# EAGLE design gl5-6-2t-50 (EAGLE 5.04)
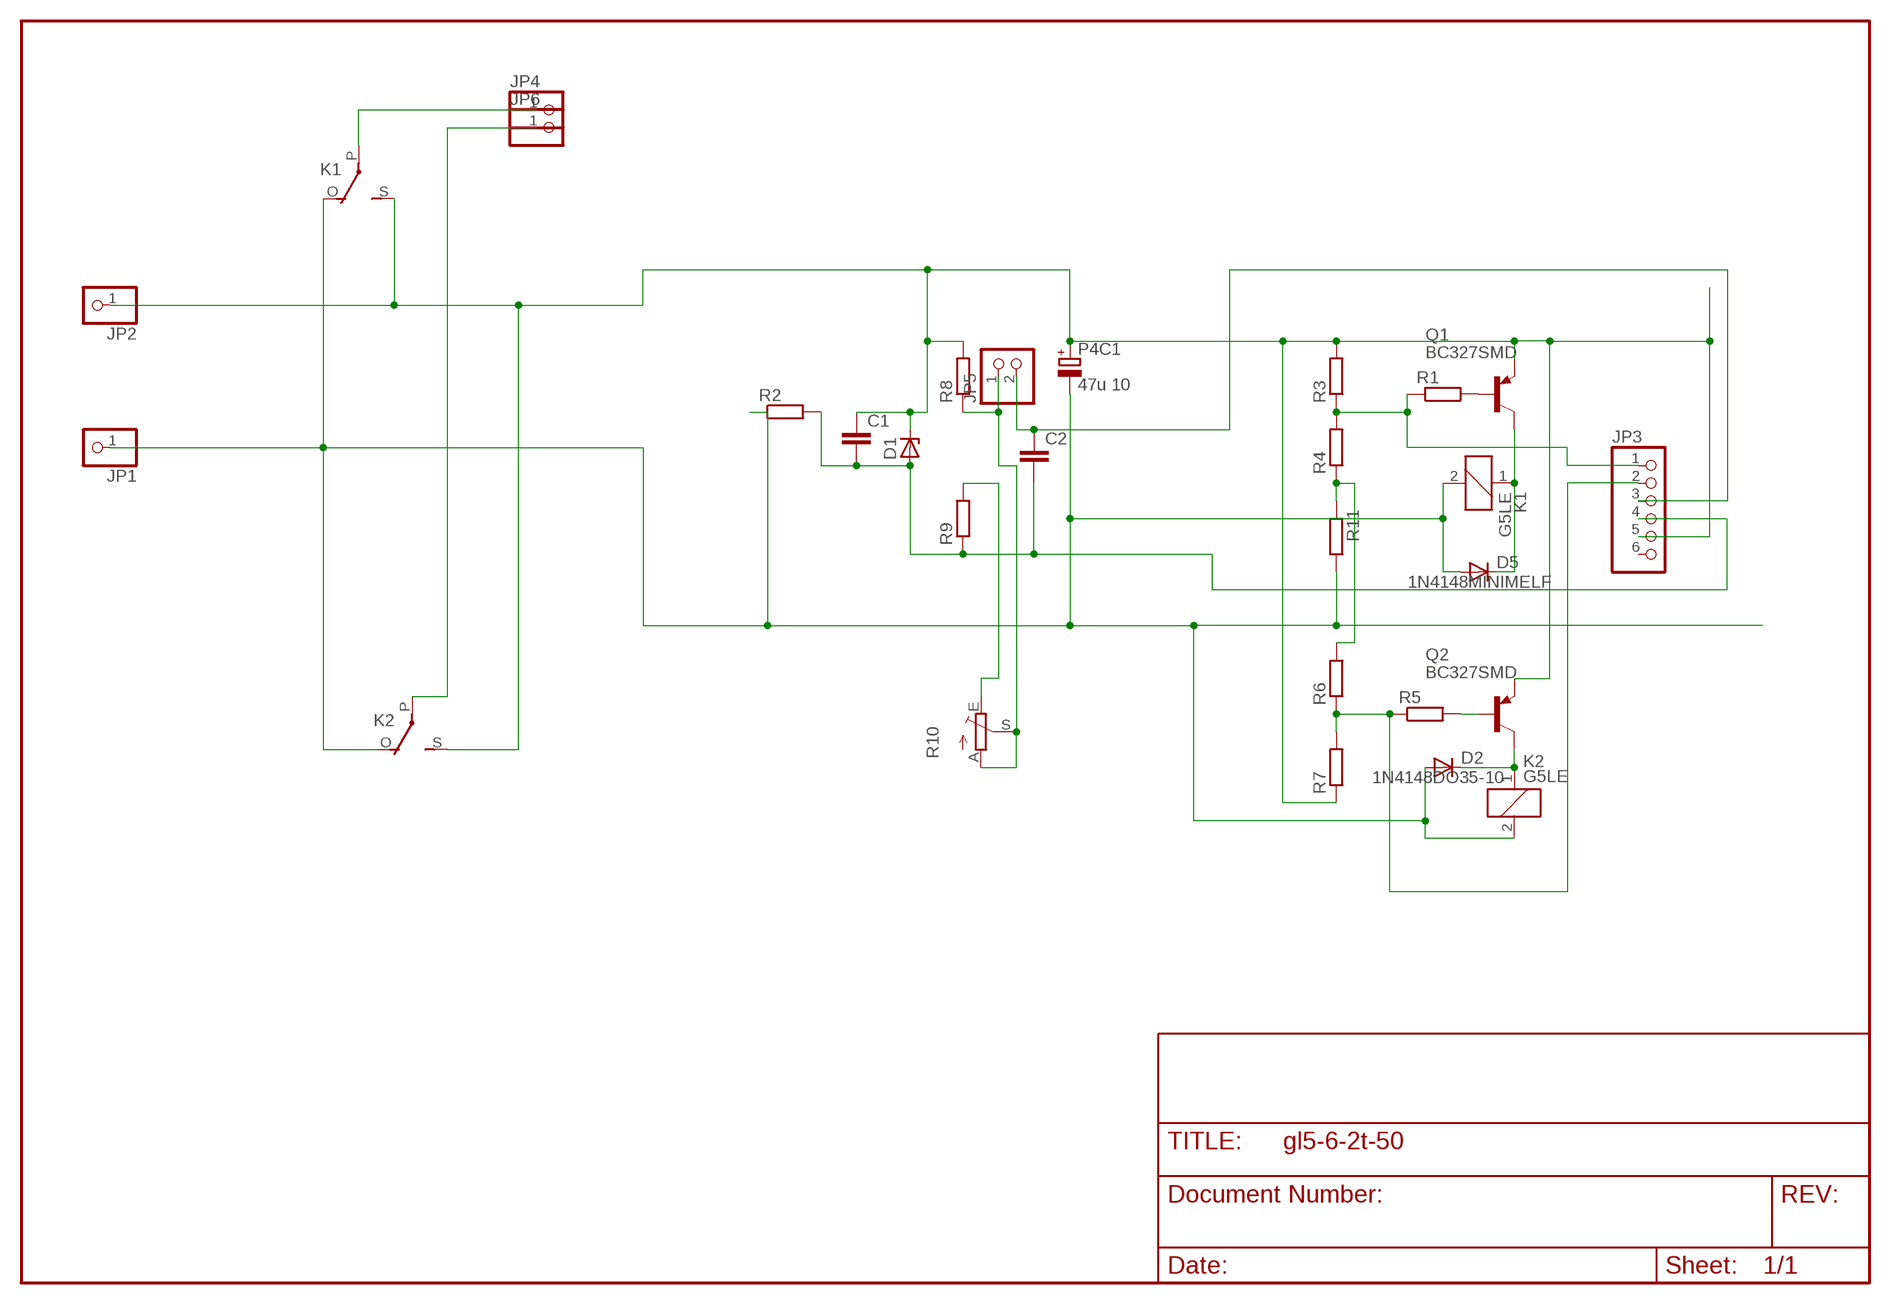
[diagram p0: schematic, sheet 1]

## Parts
C1  C-EUC1206  [C1206]
C2  C-EUC1206  [C1206]
D1  ZENER-DIODESOT23  [SOT23]
D2  1N4148DO35-10  [DO35-10]
D5  1N4148MINIMELF  [MINIMELF]
JP1  PINHD-1X1  [1X01]
JP2  PINHD-1X1  [1X01]
JP3  PINHD-1X6  [1X06]
JP4  PINHD-1X1  [1X01]
JP5  PINHD-1X2  [1X02]
JP6  PINHD-1X1  [1X01]
K1  G5LE  [G5LE]
K2  G5LE  [G5LE]
P4C1  47u 10  CPOL-EUE5-8.5  [E5-8,5]
Q1  BC327SMD  [SOT23-BEC]
Q2  BC327SMD  [SOT23-BEC]
R1  R-EU_R0805  [R0805]
R2  R-EU_M1206  [M1206]
R3  R-EU_R0805  [R0805]
R4  R-EU_R2010  [R2010]
R5  R-EU_R0805  [R0805]
R6  R-EU_R2010  [R2010]
R7  R-EU_R0805  [R0805]
R8  R-EU_R0805  [R0805]
R9  R-EU_R0805  [R0805]
R10  TRIM_EU-CA6V  [CA6V]
R11  R-EU_R0805  [R0805]

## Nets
N$1: R9.2 R10.E
N$2: JP4.1 K1.P(2:P)
N$3: JP5.1 R8.1 R10.A R10.S
N$4: JP6.1 K2.P(2:P)
N$5: C1.2 C2.2 D1.1(A) JP3.4 R2.2 R9.1
N$6: R4.1 R6.2 R11.1
N$7: C2.1 JP3.3 JP5.2
N$8: Q1.B R1.2
N$10: JP3.1 R1.1 R3.1 R4.2
N$11: D5.C K1.1 Q1.C
N$12: D2.C K2.1 Q2.C
N$13: JP3.2 R5.1 R6.1 R7.2
N$15: Q2.B R5.2
V+: C1.1 D1.3(C) JP2.1 JP3.5 K1.S(2:S) K2.S(2:S) P4C1.+ Q1.E Q2.E R3.2 R7.1 R8.2
V-: D2.A D5.A JP1.1 K1.2 K1.O(2:O) K2.2 K2.O(2:O) P4C1.- R2.1 R11.2
Unconnected: JP3.6

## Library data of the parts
C1 C2 = rcl-2:C-EU: CAPACITOR, European symbol
D1 = diode-1:ZENER-DIODE: Z-Diode
D2 D5 = diode-1:1N4148: DIODE
JP1 JP2 JP4 JP6 = pinhead(2):PINHD-1X1: PIN HEADER
JP3 = pinhead:PINHD-1X6: PIN HEADER
JP5 = pinhead:PINHD-1X2: PIN HEADER
K1 K2 = relay:G5LE: RELAY 1 x switch, 10 A/120 V AC, 8 A/30 V DC, Omron
P4C1 = rcl:CPOL-EU: POLARIZED CAPACITOR, European symbol
Q1 Q2 = transistor-pnp:BC327*: PNP Transistror
R1-R9 R11 = rcl-2:R-EU_: RESISTOR, European symbol
R10 = pot:TRIM_EU-: POTENTIOMETER

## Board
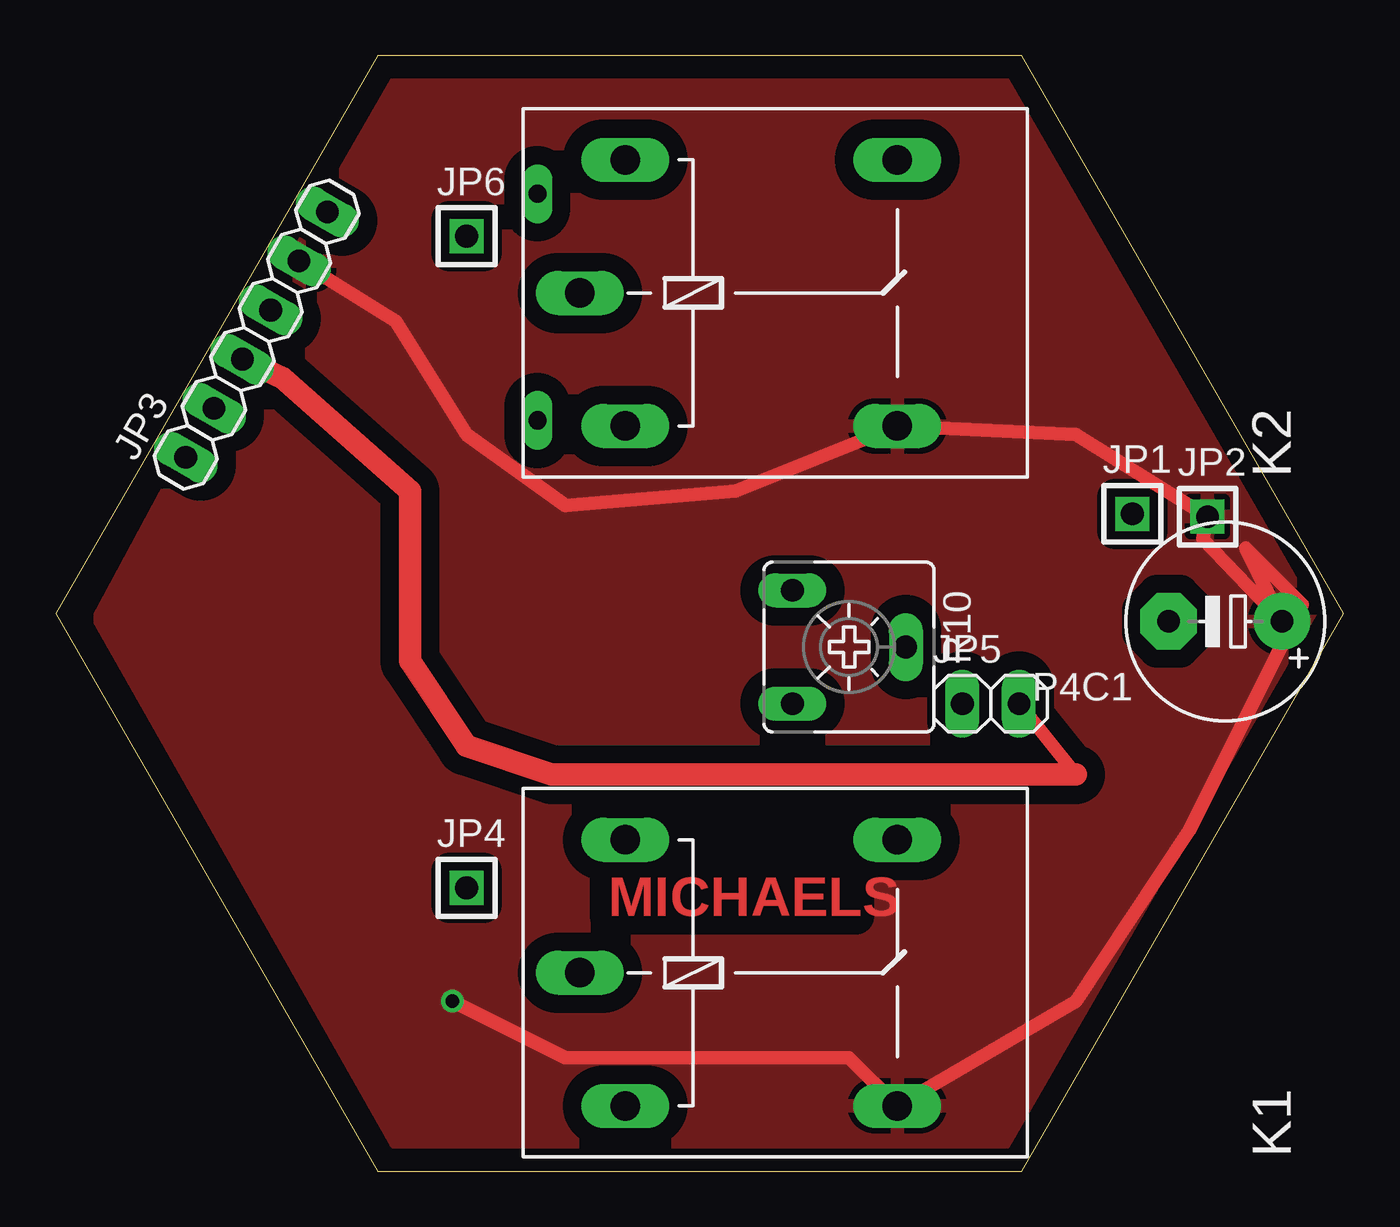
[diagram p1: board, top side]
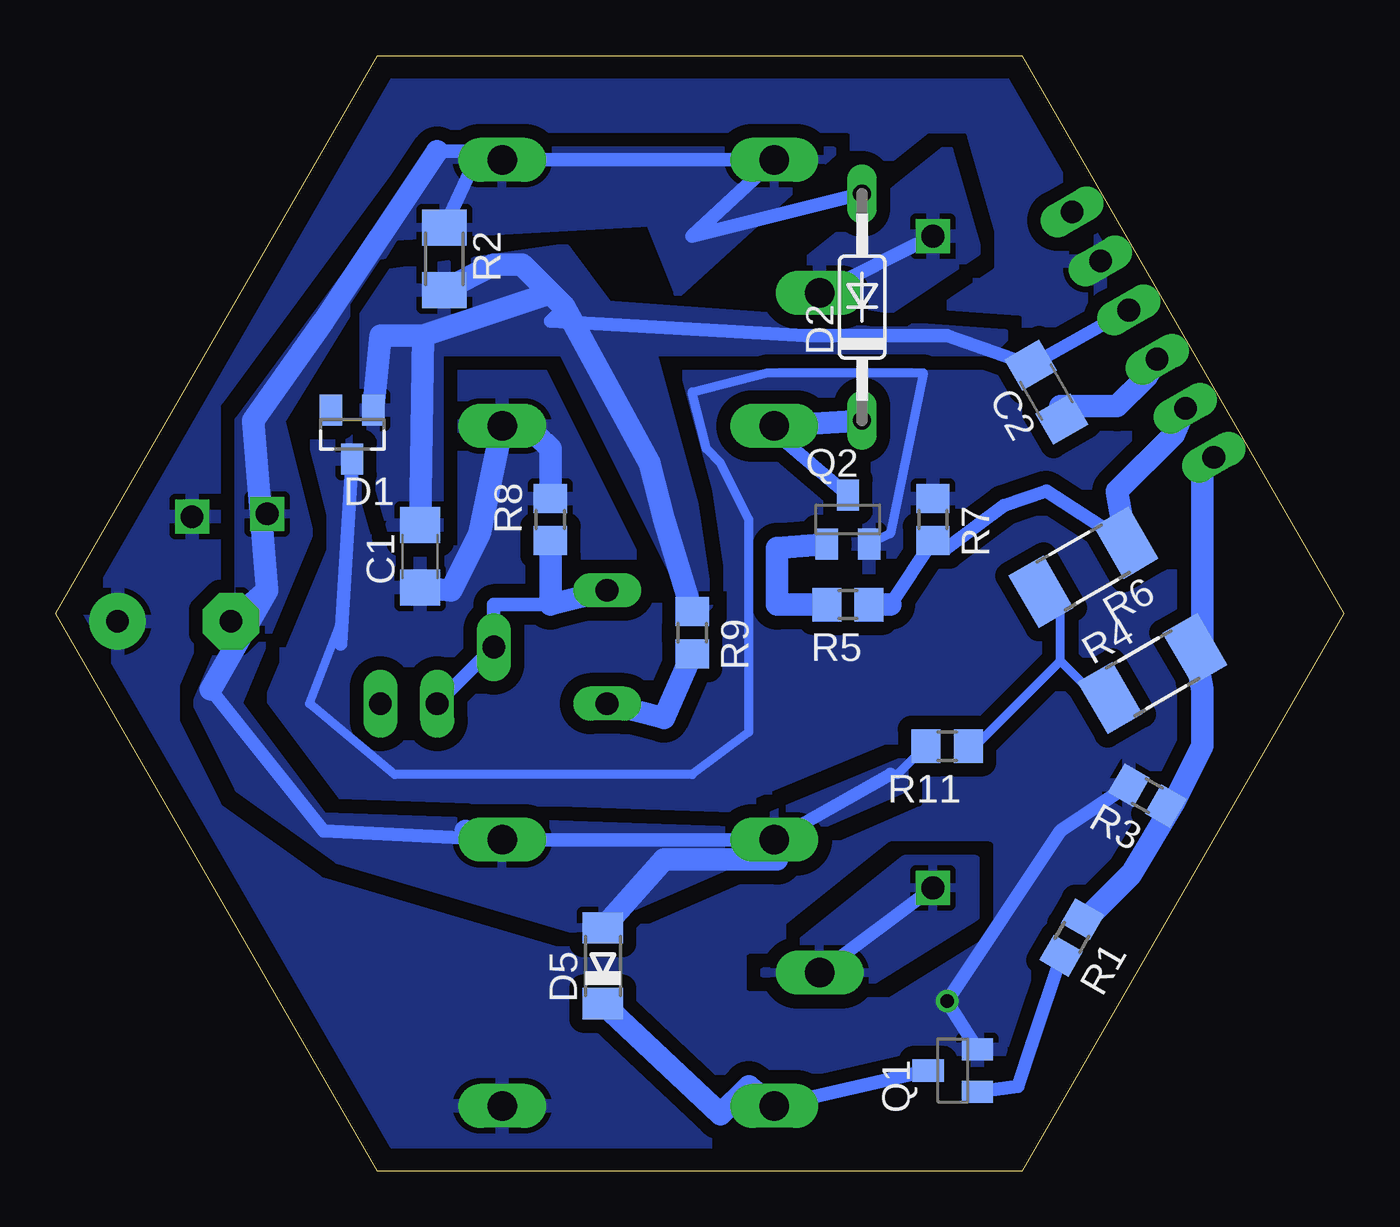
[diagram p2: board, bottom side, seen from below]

Size 57.73 x 50 mm. Coordinates in mm from the lower left corner, seen from the top.
Outline: 14.43,0 43.3,0 57.73,25 43.3,50 14.43,50 0,25 14.43,0
Copper layers (1*16): Top 0.035mm / dielectric 1.5mm / Bottom 0.035mm
Design rules "default *": minimum track width 40mil, minimum drill 30mil, track to track 8mil, track to pad 8mil, pad to pad 8mil, via to via 8mil, smd to smd 8mil, copper to edge 40mil, drill to drill 8mil, minimum pad ring 10mil, minimum via ring 8mil, stop-mask expansion 4mil, vias tented up to drill 0mil, thermal gap 10mil

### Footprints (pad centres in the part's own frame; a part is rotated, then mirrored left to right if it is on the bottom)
C1206 = smd 1.6 x 1.8: 1 -1.4,0; 2 1.4,0
SOT23 = smd 1 x 1.4: 1 -0.95,-1.1; 2 0.95,-1.1; 3 0,1.1
DO35-10 = drill 0.813 long: A 5.08,0; C -5.08,0
MINIMELF = smd 1.4 x 1.8: A 1.7,0; C -1.7,0
1X01 = drill 1.016 square: 1 0,0
1X06 = drill 1.016 long: 1 -6.35,0; 2 -3.81,0; 3 -1.27,0; 4 1.27,0; 5 3.81,0; 6 6.35,0
1X02 = drill 1.016 long: 1 -1.27,0; 2 1.27,0
G5LE = drill 1.321 long: 1 -7.493,-5.969; 2 -7.493,5.969; O 4.699,5.969; P -9.525,0; S 4.699,-5.969
E5-8,5 = drill 1.016 pad 2.54 round: + -2.54,0 | drill 1.016 pad 2.54 octagon: - 2.54,0
SOT23-BEC = smd 1 x 1.4: B -0.95,-1.1; C 0,1.1; E 0.95,-1.1
R0805 = smd 1.3 x 1.5: 1 -0.95,0; 2 0.95,0
M1206 = smd 1.6 x 2: 1 -1.4,0; 2 1.4,0
R2010 = smd 1.8 x 2.7: 1 -2.2,0; 2 2.2,0
CA6V = drill 1.016 long: A -2.54,-2.54; E 2.54,-2.54; S 0,2.54

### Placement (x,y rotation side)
C1  41.4,27.56 90 bottom
C2  13.34,34.92 120 bottom
D1  44.45,33.02 180 bottom
D2  21.59,38.73 90 bottom
D5  33.21,9.21 90 bottom
JP1  48.26,29.46 0 top
JP2  51.63,29.34 0 top
JP3  9,37.5 60 top
JP4  18.41,12.7 0 top
JP5  41.91,20.95 0 top
JP6  18.41,41.91 0 top
K1  33.02,8.89 0 top
K2  33.02,39.37 0 top
P4C1  52.42,24.64 180 top
Q1  17.53,4.51 90 bottom
Q2  22.23,29.21 0 bottom
R1  12.18,10.48 240 bottom
R2  40.32,40.89 270 bottom
R3  8.8,16.83 150 bottom
R4  8.57,22.31 30 bottom
R5  22.23,25.4 180 bottom
R6  11.66,27.07 210 bottom
R7  18.41,29.21 270 bottom
R8  35.56,29.21 90 bottom
R9  29.21,24.13 270 bottom
R10  35.56,23.5 270 top
R11  17.78,19.05 180 bottom

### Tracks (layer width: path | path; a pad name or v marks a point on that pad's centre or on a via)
N$1
  Bottom 1.016: R9.2 30.48,20.32 R10.E
N$2
  Bottom 0.61: JP4.1 K1.P
  pour Bottom: 16.51,13.97 19.68,13.97 26.04,8.89 21.59,8.26 16.51,11.43
N$3
  Bottom 0.61: 35.56,25.4 38.1,25.4 R10.S JP5.1
  Bottom 1.016: R8.1 35.56,25.4 R10.A
N$4
  Bottom 0.61: JP6.1 K2.P
  pour Bottom (isolate 0.61): 17.78,45.72 24.13,40.64 24.13,39.37 20.32,38.73 16.51,41.27
N$5
  Bottom 0.61: JP3.4 C2.2 17.78,37.47 24.13,37.47 35.56,38.1 34.92,38.73
  Bottom 1.016: 41.27,37.47 43.18,37.47 D1.1 | 35.56,39.37 36.83,40.64 38.1,40.64 R2.2 | 35.56,39.37 34.92,38.73 31.11,31.75 30.48,29.21 R9.1 | 35.56,39.37 41.27,37.47 | 41.27,37.47 C1.2
  pour Bottom (isolate 0.61, rank 2): 15.24,37.47 33.02,38.73 34.92,41.27 43.81,40.01 43.81,33.02 42.55,28.57 40.64,28.57 40.64,36.83 34.92,36.83 29.84,26.67 28.57,25.4 29.21,29.84 31.11,36.83 15.88,36.83
N$6
  Bottom 0.406: R11.1 16.51,19.05 12.7,22.86 | 12.7,22.86 12.7,25.11 R6.2 | R4.1 11.05,21.21 12.7,22.86
N$7
  Top 0.61: 45.72,17.78 JP5.2
  Top 1.016: 45.72,17.78 22.23,17.78 18.41,19.05 15.88,22.86 15.88,30.48 10.16,35.56 JP3.3
  Bottom 1.016: C2.1 12.7,34.29 10.16,34.29 8.89,35.56 JP3.3
N$8
  Bottom 0.61: R1.2 13.97,5.71 14.61,3.81 Q1.B
N$10
  Bottom 1.016: 7.62,16.51 9.53,13.34 11.43,11.43 R1.1 | JP3.1 6.35,31.75 6.35,22.86 R4.2 6.35,21.59 6.35,19.05 7.62,16.51 | 7.62,16.51 R3.1
N$11
  Bottom 0.61: Q1.C K1.1
  Bottom 1.016: D5.C 27.94,2.54 26.67,3.81 K1.1
N$12
  Bottom 0.61: Q2.C 25.4,33.02 K2.1
  Bottom 1.016: K2.1 D2.C
N$13
  Bottom 0.61: 20.32,25.4 R7.2 17.78,27.94 15.24,29.84 13.34,30.48 R6.1
  Bottom 1.016: 20.32,25.4 R5.1 | R6.1 10.16,30.48 7.62,33.02 JP3.2
N$15
  Bottom 1.016: Q2.B 25.4,27.94 25.4,25.4 R5.2
V+  (via drill 0.6)
  Top 0.61: JP3.5 15.24,38.1 18.41,33.02 22.86,29.84 30.48,30.48 K2.S 45.72,33.02 JP2.1 51.41,28.34 P4C1.+ 53.34,27.94 55.88,25.4 50.8,15.24 45.72,7.62 K1.S 35.56,5.08 22.86,5.08 v17.78,7.62
  Bottom 0.406: Q2.E 20.32,28.57 18.85,35.8 25.84,35.8 29.21,34.92 28.57,32.38 27.94,31.75 26.67,29.21 26.67,19.68 29.21,17.78 42.55,17.78 46.35,20.95 44.9,24.75
  Bottom 0.61: Q1.E v17.78,7.62 12.7,15.24 R3.2 | 44.97,23.62 44.9,24.75 D1.3
  Bottom 1.016: R8.2 35.56,32.38 36.2,33.02 36.83,33.02 K2.S 38.73,28.57 40.01,26.04 C1.1
  pour Top (isolate 0.813, rank 6): 15.24,49.53 42.55,48.9 56.52,24.77 42.55,1.27 15.24,1.27 1.91,24.77
  pour Bottom (isolate 0.61, rank 6): 15.24,49.53 42.55,48.9 56.52,24.77 42.55,1.27 15.24,1.27 1.91,24.77
V-
  Bottom 0.406: 20.32,17.78 20,17.78 R11.2
  Bottom 0.61: 20.32,17.78 K1.2 K1.O 45.72,15.24 50.8,21.59 | D2.A 29.21,41.91 K2.2 K2.O 38.73,45.72 | 38.73,45.72 R2.1 | 40.64,45.72 38.73,45.72
  Bottom 1.016: 50.8,21.59 48.26,26.04 | 48.26,26.04 P4C1.- | D5.A 30.48,13.97 25.4,13.97 K1.2 | K1.O 39.37,15.24 | 40.64,45.72 45.72,38.1 48.9,33.66 48.26,26.04
  pour Bottom (isolate 0.406, rank 4): 22.86,45.72 40.64,45.72 49.53,33.66 49.53,25.4 51.44,20.95 49.53,17.14 45.09,13.97 34.29,10.79 19.68,17.14 19.68,18.41 27.3,15.24 45.72,15.88 49.53,20.95 46.35,28.57 47.62,33.66 42.55,41.91 31.11,42.55 29.84,39.37

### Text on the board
Top: MICHAELS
